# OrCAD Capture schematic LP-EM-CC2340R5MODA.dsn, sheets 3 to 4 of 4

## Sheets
3 3_Debugger Interface: size A3
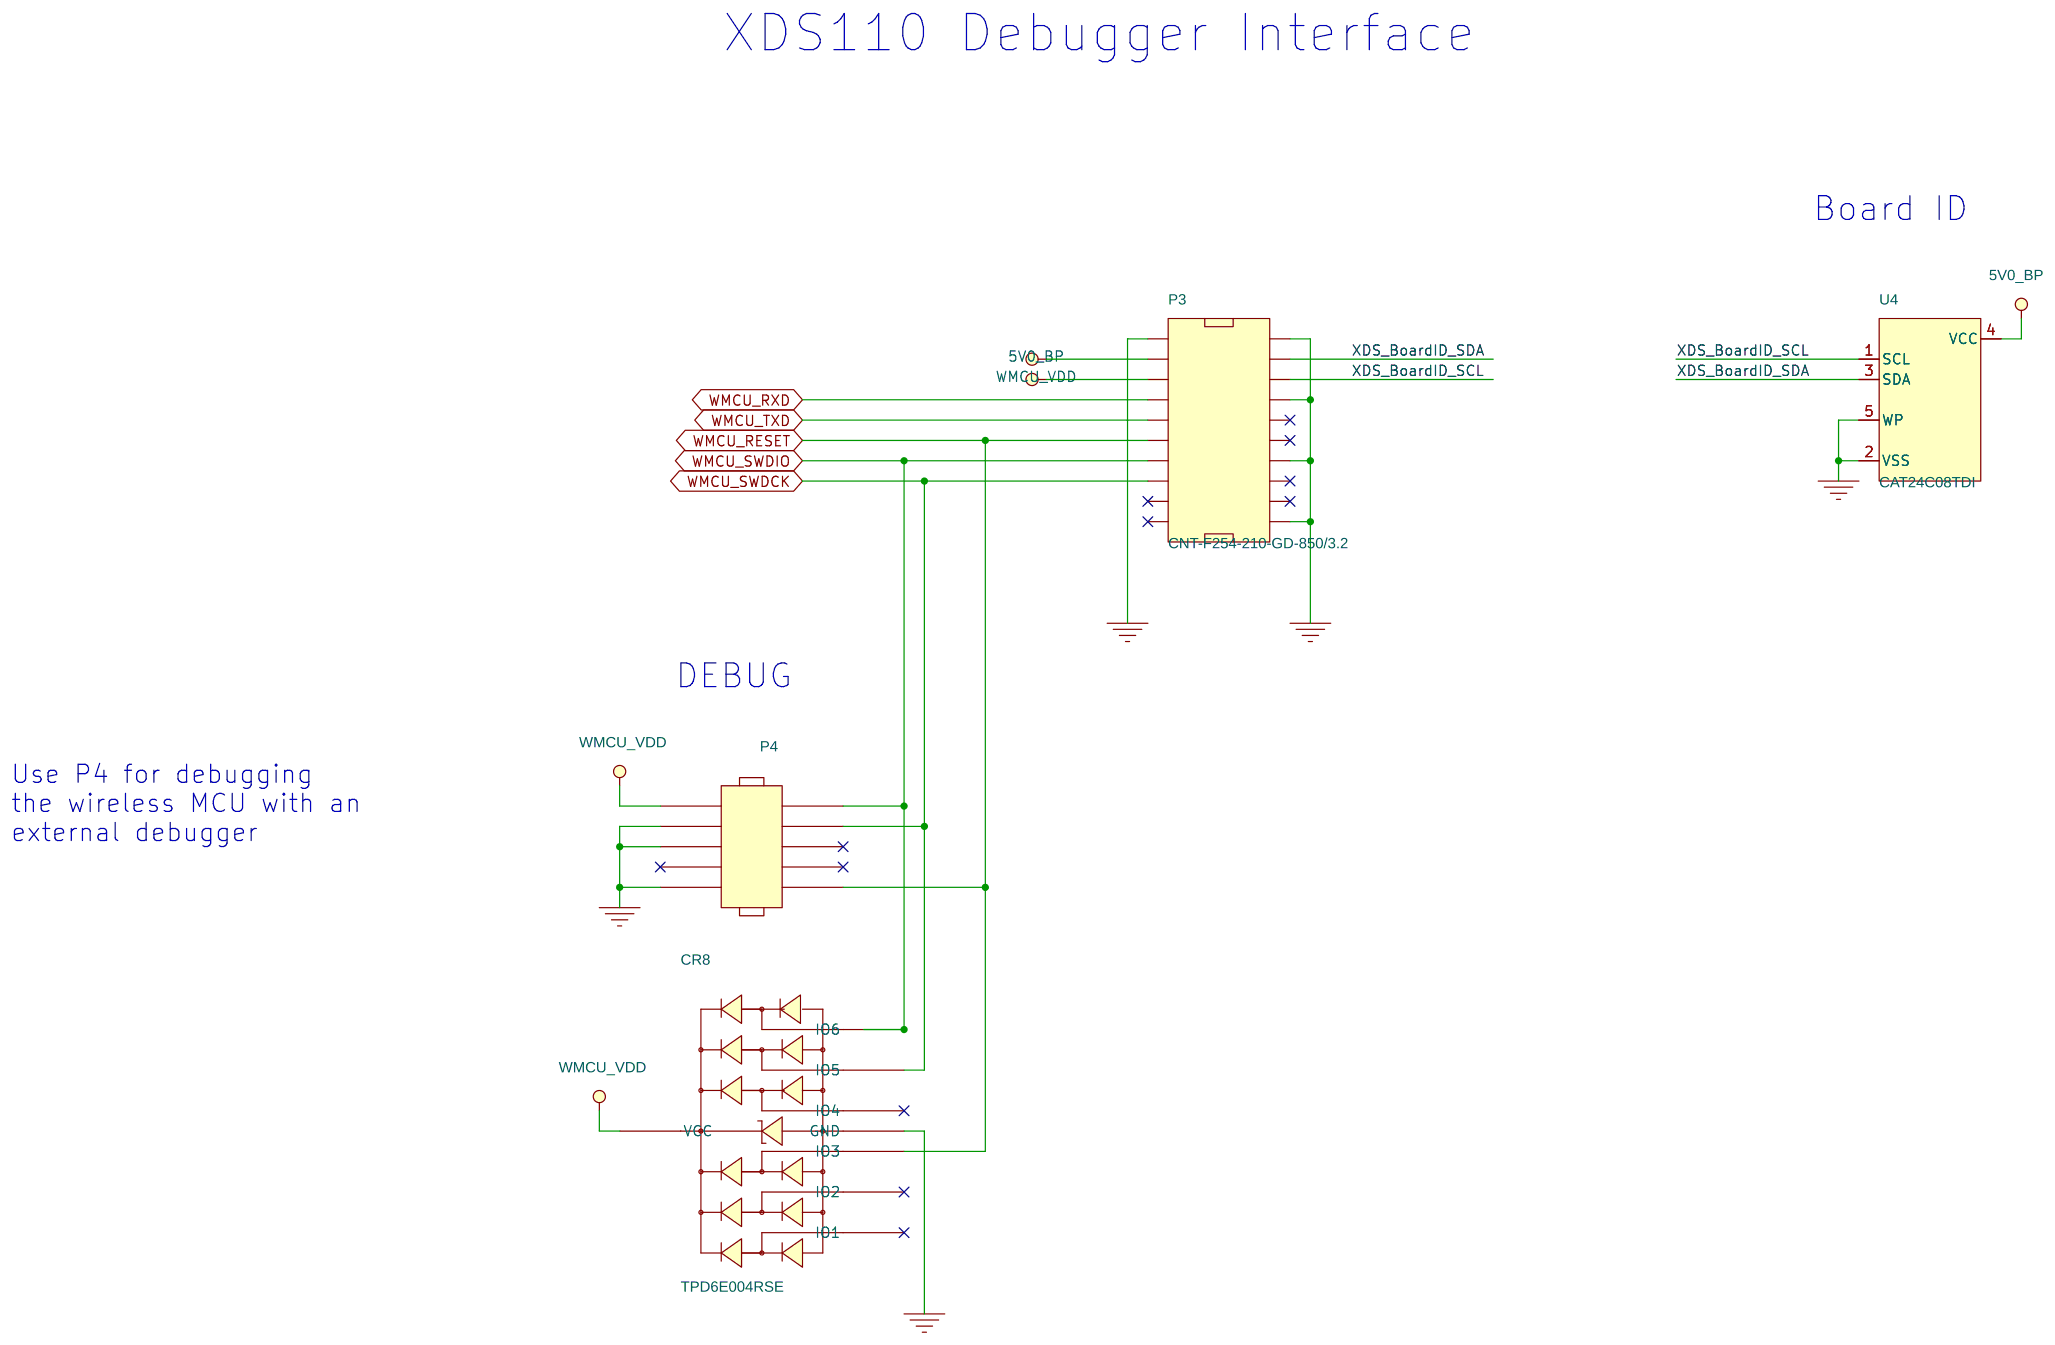
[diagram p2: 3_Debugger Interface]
4 4_Mech: size A3
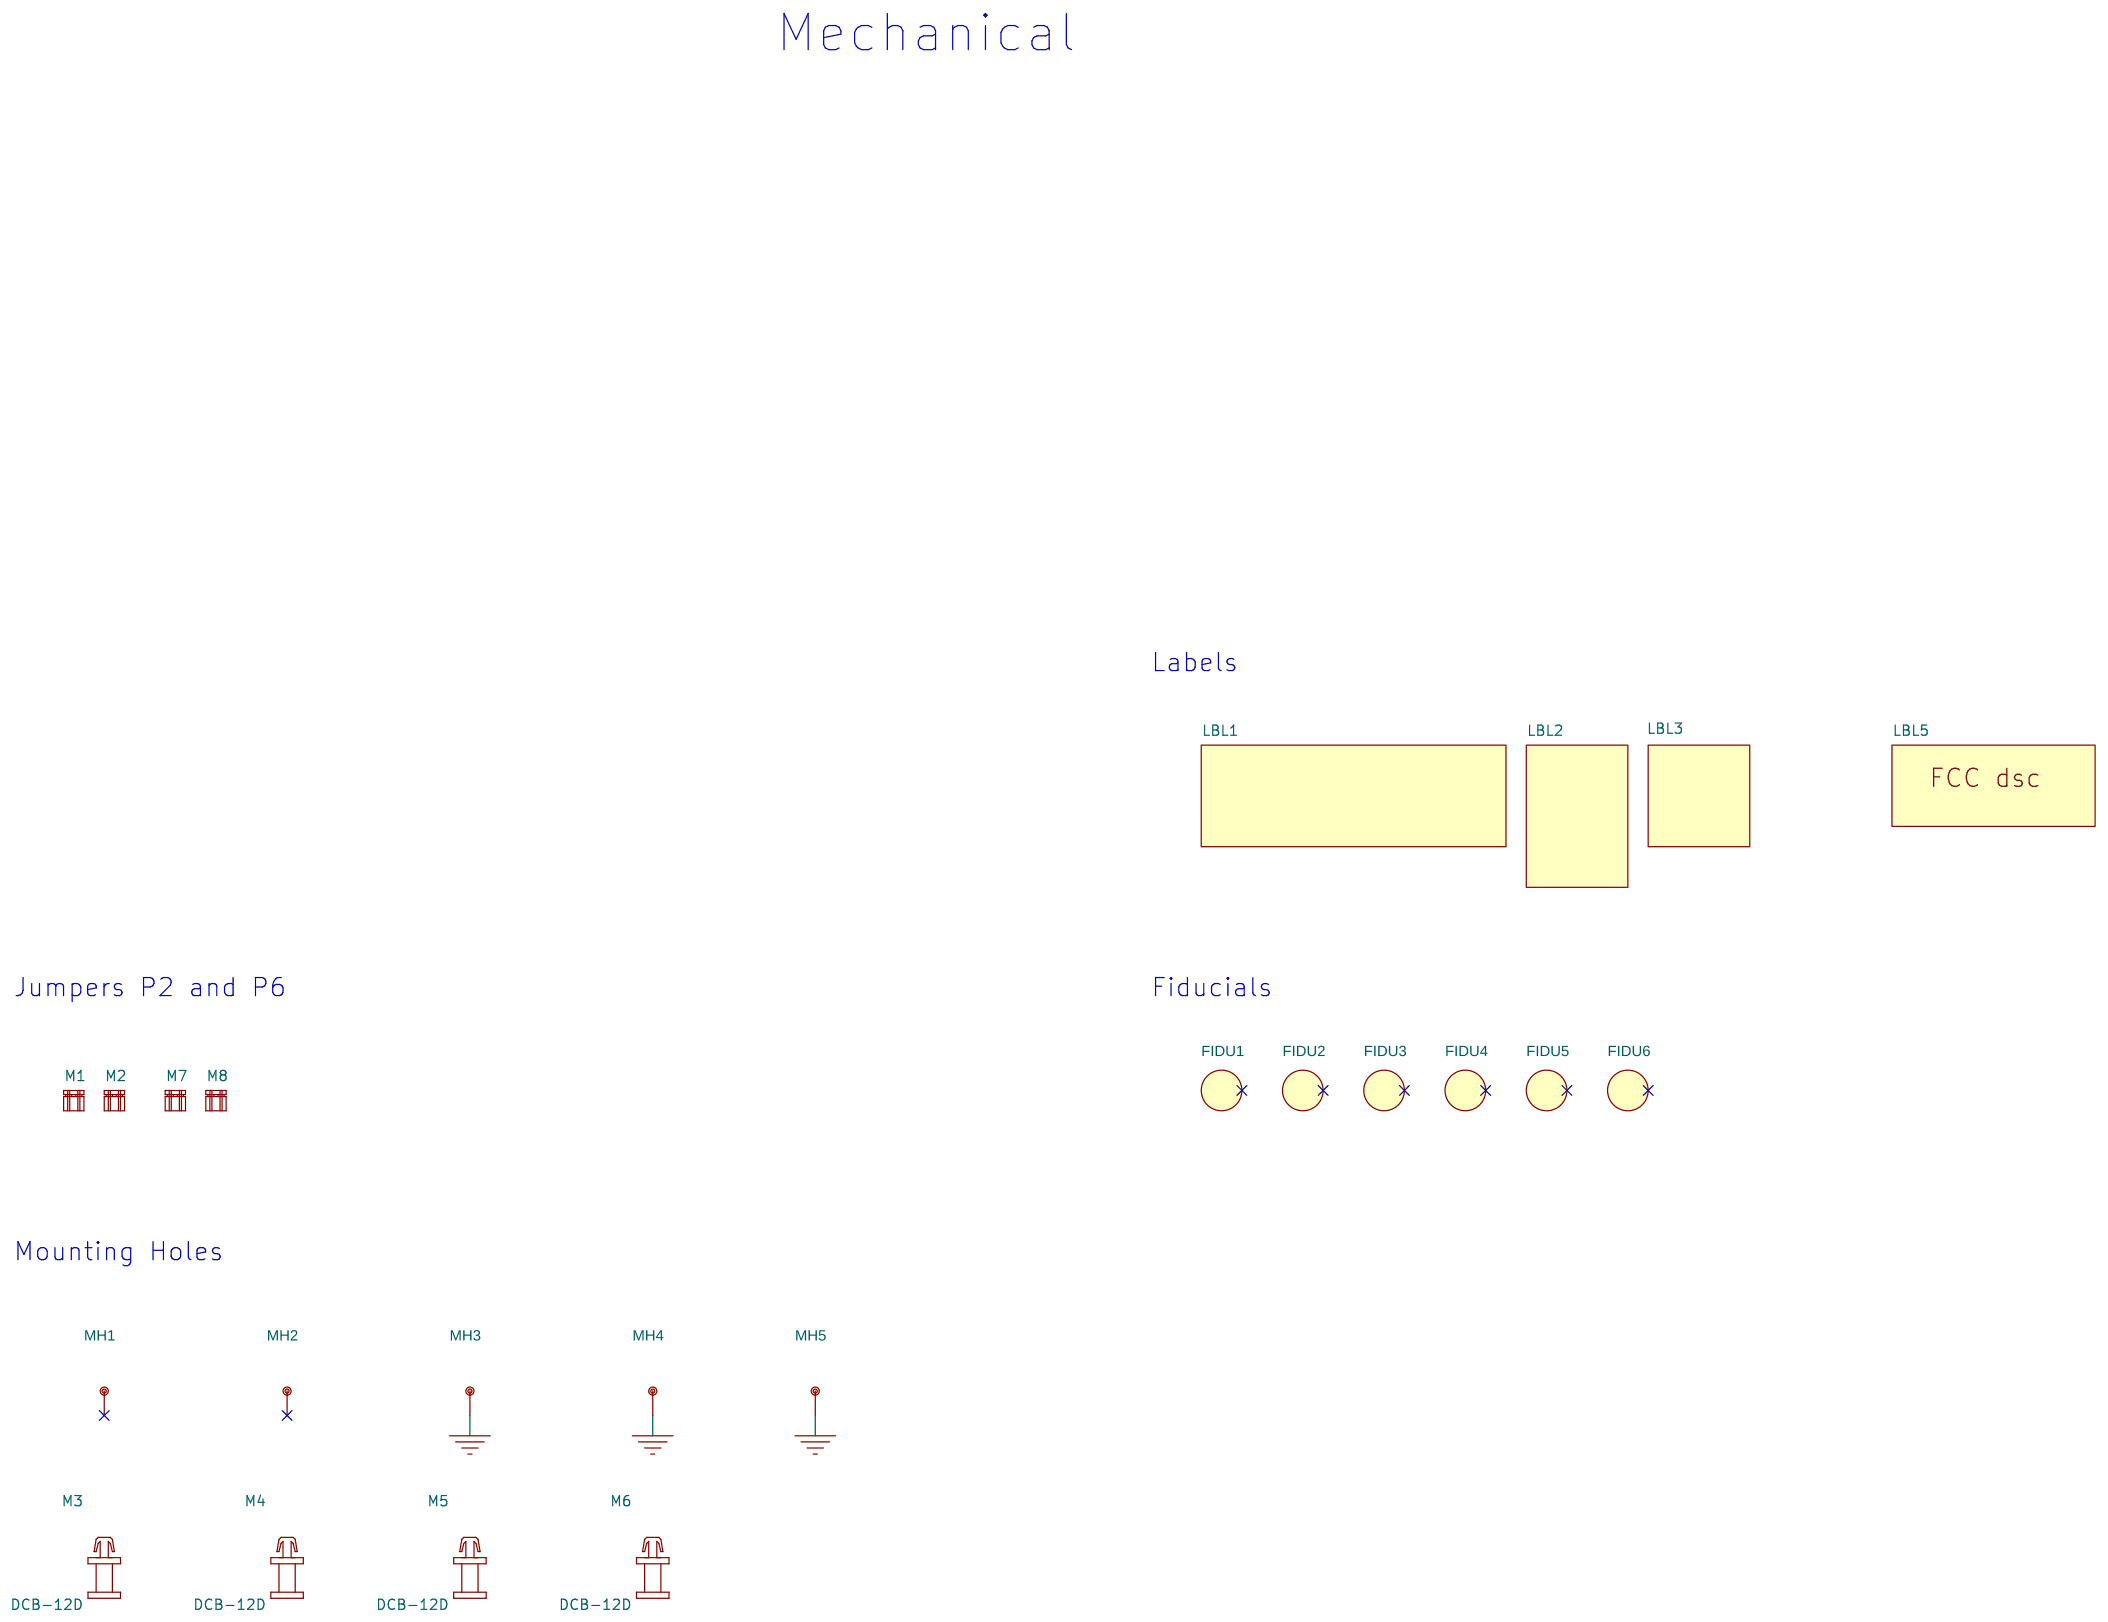
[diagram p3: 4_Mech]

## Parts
sheet 3_Debugger Interface
CR8  TPD6E004RSE  [QFNFC50P150X150X60-8A2N]
P3  CNT-F254-210-GD-850/3.2  [CNT_CNTF254210GD85032_A2B]
P4  FTSH-105-01-F-DV-K  [SAMTEC_FTSH-105-01-F-DV-K-10N]
U4  CAT24C08TDI  [SOT95P280X100-5A2N]
sheet 4_Mech
FIDU1  FIDU_1.27mm  [FID127X142]
FIDU2  FIDU_1.27mm  [FID127X142]
FIDU3  FIDU_1.27mm  [FID127X142]
FIDU4  FIDU_1.27mm  [FID127X142]
FIDU5  FIDU_1.27mm  [FID127X142]
FIDU6  FIDU_1.27mm  [FID127X142]
LBL1  TI_LOGO  [TI_LOGO_1]
LBL2  TRASH_7mm  [TRASH_7MM]
LBL3  ESD_LABEL_5x5mm  [ESD_LABEL_5X5]
LBL5  LABEL_FOR_EVALUATION_ONLY  [LABEL_FOR_EVALUATION_ONLY]
M1  SNT-100-BK-G  [SAMTEC_SNT100BKG]
M2  SNT-100-BK-G  [SAMTEC_SNT100BKG]
M3  DCB-12D  [MECH_DCB12D_A2B]
M4  DCB-12D  [MECH_DCB12D_A2B]
M5  DCB-12D  [MECH_DCB12D_A2B]
M6  DCB-12D  [MECH_DCB12D_A2B]
M7  SNT-100-BK-G  [SAMTEC_SNT100BKG]
M8  SNT-100-BK-G  [SAMTEC_SNT100BKG]
MH1  HOLE_3.2mm_PAD_3.8mm_PTH  [MTG320_380]
MH2  HOLE_3.2mm_PAD_3.8mm_PTH  [MTG320_380]
MH3  HOLE_3.2mm_PAD_3.8mm_PTH  [MTG320_380]
MH4  HOLE_3.2mm_PAD_3.8mm_PTH  [MTG320_380]
MH5  HOLE_1.1mm_PTH  [MTG110_170]

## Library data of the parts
CR8 = DIODE_TVS_TPD6E004_QFN8_V1: DIODE, PROTECTION, ESD ARRAY - 6 CHANNELS, VCC:0.9V TO 5.5V, VBR:7V, -40DEGC/+85DEGC, QFN8, SMD; ALT_SYMBOLS: QFNFC50P150X150X60-8A2L,QFNFC50P150X150X60-8A2M; Additional Datasheet URL: https://www.ti.com/product/TPD6E004; AutoDoc File: https://notefied-dynamic-precision.com/DB/Apps/Desktop/Item/Object.aspx?id=74721; BU Name: DYNAMIC PRECISION GDANSK; Budget Currency: USD; Budget Price: 0.27; Budgetary Price: .16 USD; CLASS: IC; Client Status: UNDER_REVIEW; Country of Origin: China; Datasheet URL: https://www.ti.com/lit/gpn/TPD6E004; Datasheet URL 1: http://www.ti.com/lit/ds/symlink/tpd6e004.pdf; Datasheet URL 2: http://www.ti.com/litv/pdf/mpqf207b; FPLIST: QFN50P150X150X60-8N,QFN50P150X150X60-8AN; Lead Time: 12; Mass: 0.002839255g; Max Oper Temp: +85DEGC; Maximum Operating Temperature: +85DEGC; Min Oper Temp: -40DEGC; Minimum Operating Temperature: -40DEGC; Mounting Type: SMD; NOTEfied URL: https://dev-webinterface.dpserver.no/item/7366948; PCB Package: QFN8; Packing Size: 3000; Packing Type: Tape & Reel; Part Number: 14-05493; Part Type: Diode|PROTECTION; REACH/SVHC Compliance: Compliant; REACH/SVHC Details: SVHC List Version Jun 20, 2016; REACH/SVHC Source: Material Declaration; REACH/SVHC Status: Unaffected; ROHS: Compliant; Rated Power: N/A; Rated Voltage: 7V; Revision: R029; RoHS Status: ROHS_COMPLIANT; Rtd Power: N/A; Rtd Voltage: 7V; Status: Released; Texas Part Status: Under Review; Type: Diode; Vendor: TEXAS INSTRUMENTS; Vendor Part Number: TPD6E004RSER; Vendor Part Status: Active; Weight: 0.0033g
P3 = CONN_HEADER_2X10_J_S_V1: CONNECTOR, HEADER, FEMALE, RIGHT ANGLE, 2 ROW(S), 20 PIN(S), PITCH 2.54mm, PTH; ALT_SYMBOLS: CNT_CNTF254210GD85032_A2A,CNT_CNTF254210GD85032_A2C; Additional Datasheet URL: http://yccnt.com/cpzx/info_56.aspx?itemid=1264&lcid=28&cid=29; Country of Origin: Missing Info; Datasheet URL: http://yccnt.com/uploadfiles/2017/08/201708261737473747.pdf; Maximum Operating Temperature: +105DEGC; Minimum Operating Temperature: -40DEGC; Mounting Type: PTH; NOTEfied URL: https://dev-webinterface.dpserver.no/item/24885457; Number of Positions: 20; Number of Rows: 2; Packing Size: N/A; Packing Type: Missing Info; Part Number: 06-08434; Part Type: Connector|HEADER|STANDARD; Pitch: 2.54mm; REACH/SVHC Compliance: Missing Info; REACH/SVHC Details: N/A; REACH/SVHC Source: N/A; REACH/SVHC Status: Missing Info; ROHS: Compliant; Rated Current: 3A; Rated Voltage: 500V; Revision: R005; Status: Released; Texas Part Status: Under Review; Type: Connector; Vendor: CNT CONNECTORS; Vendor Part Status: Active
P4 = CONN_HEADER_2X5: CONNECTOR, HEADER, MALE, STRAIGHT, 2 ROW(S), 10 PIN(S), PITCH 1.27mm, SMD; ALT_SYMBOLS: SAMTEC_FTSH10501FDVK_A2L,SAMTEC_FTSH10501FDVK_A2M,SAMTEC_FTSH10501FDVK_B2L,SAMTEC_FTSH10501FDVK_B2M; Additional Datasheet URL: https://www.samtec.com/products/ftsh-105-01-f-dv-k; AutoDoc File: http://notefied-dynamic-precision.com/DB/Apps/Desktop/Item/Object.aspx?id=50836; Budget Currency: USD; Budget Price: 1.700; Budgetary Price: 2.07959 USD; CLASS: IO; Country of Origin: China, Costa Rica, Malaysia, Singapore, Taiwan, United States, Vietnam; Datasheet URL: https://suddendocs.samtec.com/catalog_english/ftsh_smt.pdf; Datasheet URL 1: http://www.samtec.com/documents/webfiles/cpdf/FTSH-1XX-XX-XXX-DV-XXX-MKT.pdf; Datasheet URL 2: http://www.samtec.com/documents/webfiles/pdf/FTSH_SMT.PDF; FPLIST: SAMTEC_FTSH-105-01-F-DV-K-10N,SAMTEC_FTSH-105-01-F-DV-K-10L,SAMTEC_FTSH-105-01-F-DV-K-10M; Lead Time: 14; LifeCycle Status: MATURITY; MPN Status: ACTIVE; Manufacturer: SAMTEC; Mass: 0.31700g; Max Oper Temp: +125DEGC; Maximum Operating Temperature: +125DEGC; Min Oper Temp: -55DEGC; Minimum Operating Temperature: -55DEGC; Mounting Type: SMD; NOTE Status: PREFERRED; NOTEfied URL: https://dev-webinterface.dpserver.no/item/7308603; No Of Pos: 10; No Of Rows: 2; Number of Positions: 10; Number of Rows: 2; Old Footprint: SAMTEC_FTSH-105-01-F-DV-K-10N,CONN_MALE_2X5; Packing Size: 92; Packing Type: Tube; Part Number: 06-00166; Part Type: Connector|HEADER|STANDARD; Pitch: 1.27mm; REACH/SVHC Compliance: Compliant; REACH/SVHC Details: SVHC List Version Jun 20, 2016; REACH/SVHC Source: Material Declaration; REACH/SVHC Status: Unaffected; ROHS: Compliant; Rated Current: 3.4A; Revision: R034; RoHS Status: ROHS_COMPLIANT; Rtd Current: 1.75A; Status: Released; Texas Part Status: Under Review; Type: Connector; Vendor: SAMTEC; Vendor Part Status: Active; WEIGHT: 0.65614g
U4 = IC_EEPROM_CAT24C08_TSOT23-5: IC, MEMORY, EEPROM, SERIAL, I2C, 8kbit, 1k X 8bit, 900ns, 1.7V TO 5.5V, TSOT23-5, SMD; ALT_SYMBOLS: SOT95P280X100-5A2L,SOT95P280X100-5A2M; Additional Datasheet URL: https://www.onsemi.com/products/timing-logic-memory/memory/eeprom-memory/cat24c08; Budgetary Price: .1867 USD; Country of Origin: Thailand; Datasheet URL: https://www.onsemi.com/download/data-sheet/pdf/cat24c01-d.pdf; Lead Time: 23; Mass: 0.01268g; Maximum Operating Temperature: +85DEGC; Minimum Operating Temperature: -40DEGC; Mounting Type: SMD; NOTEfied URL: https://dev-webinterface.dpserver.no/item/25158614; PCB Package: TSOT23-5; Packing Size: 3000; Packing Type: Tape & Reel; Part Number: 18-36044; Part Type: IC|EEPROM|SERIAL|I2C; REACH/SVHC Compliance: Compliant; REACH/SVHC Details: SVHC List Version Jan 16, 2020; REACH/SVHC Source: REACH Declaration; REACH/SVHC Status: Unaffected; ROHS: Compliant; Rated Voltage: 1.7V TO 5.5V; Revision: R007; Status: Released; Texas Part Status: Under Review; Type: IC; Vendor: ONSEMI; Vendor Part Number: CAT24C08TDI-GT3; Vendor Part Status: Active
FIDU1-FIDU6 = FIDMARK: NON COMPONENT, FIDUCIAL MARK, ROUND 1.27MM, SMD; Additional Datasheet URL: N/A; CLASS: IO; Country of Origin: Missing Info; Datasheet URL: N/A; Mass: N/A; Mounting Type: SMD; NOTEfied URL: https://dev-webinterface.dpserver.no/item/7504224; Packing Size: N/A; Packing Type: Missing Info; Part Number: 19-00300; Part Type: Non Component|FIDUCIAL; ROHS: Not Applicable; Revision: R020; Status: Released; Texas Part Status: Under Review; Type: Non Component; Vendor: NON_COMPONENT; Vendor Part Number: FIDUCIAL_1.27mm; Vendor Part Status: Active
LBL1 = TI_LOGO_V1: NON COMPONENT, LABEL, TEXAS INSTRUMENTS LOGO; Additional Datasheet URL: N/A; AutoDoc File: https://notefied-dynamic-precision.com/DB/Apps/Desktop/Item/Object.aspx?id=87770; BU Name: TEXAS INSTRUMENTS NORWAY; Country of Origin: Missing Info; Datasheet URL: N/A; Mass: N/A; Mounting Type: NOT APPLY; NOTEfied URL: https://dev-webinterface.dpserver.no/item/7504541; Notes: Custom Item; Packing Size: N/A; Packing Type: Missing Info; Part Number: 19-00350; Part Type: Non Component|LABEL; ROHS: Not Applicable; Revision: R023; Status: Released; Texas Part Status: Under Review; Type: Non Component; Vendor: NON_COMPONENT; Vendor Part Status: Active
LBL2 = TRASH_V2: NON COMPONENT, LABEL, TRASH 7mm; Additional Datasheet URL: N/A; Country of Origin: Missing Info; Datasheet URL: N/A; Mass: N/A; Mounting Type: NOT APPLY; NOTEfied URL: https://dev-webinterface.dpserver.no/item/14983721; Packing Size: N/A; Packing Type: Missing Info; Part Number: 19-01044; Part Type: Non Component|LABEL; ROHS: Not Applicable; Revision: R016; Status: Released; Texas Part Status: Under Review; Type: Non Component; Vendor: NON_COMPONENT; Vendor Part Status: Active
LBL3 = ESD_LABEL: NON COMPONENT, LABEL, ESD, 5 X 5 mm; Additional Datasheet URL: N/A; Country of Origin: Missing Info; Datasheet URL: N/A; Mass: N/A; Maximum Operating Temperature: N/A; Minimum Operating Temperature: N/A; Mounting Type: NOT APPLY; NOTEfied URL: https://dev-webinterface.dpserver.no/item/7504774; Packing Size: N/A; Packing Type: Missing Info; Part Number: 19-00471; Part Type: Non Component|LABEL; ROHS: Not Applicable; Revision: R009; Status: Released; Type: Non Component; Vendor: NON_COMPONENT; Vendor Part Status: Active
LBL5 = LABEL_FOR_EVALUATOIN_ONLY: NON COMPONENT, LABEL, FOR EVALUATION ONLY, NOT FCC APPROVED FOR RESALE; Additional Datasheet URL: N/A; AutoDoc File: https://notefied-dynamic-precision.com/DB/Apps/Desktop/Item/Object.aspx?id=115268; BU Name: TEXAS INSTRUMENTS NORWAY; Country of Origin: Missing Info; Datasheet URL: N/A; Mass: N/A; Maximum Operating Temperature: N/A; Minimum Operating Temperature: N/A; Mounting Type: NOT APPLY; NOTEfied URL: https://dev-webinterface.dpserver.no/item/7505603; Notes: Custom Item; Packing Size: N/A; Packing Type: Missing Info; Part Number: 19-00830; Part Type: Non Component|LABEL; REACH/SVHC Compliance: Missing Info; REACH/SVHC Details: N/A; REACH/SVHC Source: N/A; REACH/SVHC Status: Missing Info; ROHS: Not Applicable; Revision: R023; Status: Released; Texas Part Status: Under Review; Type: Non Component; Vendor: NON_COMPONENT; Vendor Part Status: Active
M1 M2 M7 M8 = MECH_SHUNT_JUMPER_V1: MECHANIC, SHUNT, CURRENT RATING 4.3A PER PIN, 2.54 X 5.08 X 6.1mm, BLACK; Additional Datasheet URL: https://www.samtec.com/products/snt-100-bk-g; AutoDoc File: https://notefied-dynamic-precision.com/DB/Apps/Desktop/Item/Object.aspx?id=104092; BU Name: DYNAMIC PRECISION GDANSK; Budget Currency: USD; Budget Price: 0.146; Budgetary Price: .19442 USD; Client Status: UNDER_REVIEW; Country of Origin: China, Costa Rica, Malaysia, Singapore, Taiwan, United States, Vietnam; Datasheet URL: https://suddendocs.samtec.com/catalog_english/snt.pdf; Datasheet URL 1: http://suddendocs.samtec.com/catalog_english/snt.pdf; Datasheet URL 2: http://suddendocs.samtec.com/prints/snt-100-xx-x-x-mkt.pdf; Lead Time: 9; Mass: 0.52432g; Max Oper Temp: +125DEGC; Maximum Operating Temperature: +125DEGC; Min Oper Temp: -55DEGC; Minimum Operating Temperature: -55DEGC; Mounting Type: NOT APPLY; NOTEfied URL: https://dev-webinterface.dpserver.no/item/7503385; Packing Size: 1; Packing Type: Bulk; Part Number: 19-00498; Part Type: Mechanic|SHUNT; REACH/SVHC Compliance: Compliant; REACH/SVHC Details: SVHC List Version Dec 17, 2015; REACH/SVHC Source: Material Declaration; REACH/SVHC Status: Unaffected; REACH/SVHC_COMPLIANCE: COMPLIANT; REACH/SVHC_DETAILS: SVHC LIST VERSION Dec 17, 2015; REACH/SVHC_SOURCE: MATERIAL DECLARATION; REACH/SVHC_STATUS: UNAFFECTED; ROHS: Compliant; Rated Current: 4.3A; Revision: R028; RoHS Status: ROHS_COMPLIANT; Rtd Current: 4.3A; Status: Released; Texas Part Status: Under Review; Type: Mechanic; Vendor: SAMTEC; Vendor Part Status: Active; Weight: 0.11724g
M3-M6 = MECH_SPACERS_SUPPORT_V1: MECHANIC, ACCESSORY, SPACER SUPPORT, PCB DIA. 3mm, NYLON 66, NPTH; Additional Datasheet URL: https://www.kangyang-europe.com/product/pc-board-hardware/dcb-12d/; Country of Origin: Missing Info; Datasheet URL: https://www.kangyang-europe.com/wp-content/uploads/2020/02/DCB-HD.pdf; Maximum Operating Temperature: N/A; Minimum Operating Temperature: N/A; Mounting Type: NPTH; NOTEfied URL: https://dev-webinterface.dpserver.no/item/44342418; Notes: Custom libraries; Packing Size: 1000; Packing Type: Missing Info; Part Number: 13-07898; Part Type: Mechanic|ACCESSORY; REACH/SVHC Compliance: Compliant; REACH/SVHC Details: SVHC List Version Jul 7, 2017; REACH/SVHC Source: REACH Declaration; REACH/SVHC Status: Unaffected; ROHS: Compliant; Revision: R018; Status: Released; Texas Part Status: Under Review; Type: Mechanic; Vendor: SUZHOU SOLY ELECTRICIAN; Vendor Part Status: Active
MH1-MH4 = HOLE_PTH: NON COMPONENT, HOLE 3.2mm, PLATED, PAD SIZE 3.8mm; Additional Datasheet URL: N/A; Country of Origin: Missing Info; Datasheet URL: N/A; Mass: N/A; Mounting Type: NOT APPLY; NOTEfied URL: https://dev-webinterface.dpserver.no/item/7503683; Packing Size: N/A; Packing Type: Missing Info; Part Number: 19-00083; Part Type: Non Component|HOLE|PLATED; ROHS: Not Applicable; Revision: R022; Status: Released; Type: Non Component; Vendor: NON_COMPONENT; Vendor Part Status: Active
MH5 = HOLE_PTH: NON COMPONENT, HOLE 1.1mm, PLATED, PAD SIZE 1.7mm; Additional Datasheet URL: N/A; Country of Origin: Missing Info; Datasheet URL: N/A; Mass: N/A; Mounting Type: NOT APPLY; NOTEfied URL: https://dev-webinterface.dpserver.no/item/7503643; Packing Size: N/A; Packing Type: Missing Info; Part Number: 19-00062; Part Type: Non Component|HOLE|PLATED; ROHS: Not Applicable; Revision: R007; Status: Released; Type: Non Component; Vendor: NON_COMPONENT; Vendor Part Number: HOLE_1.1mm_PLATED; Vendor Part Status: Active

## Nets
5V0_BP: P3.3 U4.4(VCC) ; also on sheet 2
GND: CR8.4(GND) MH3.1 MH4.1 MH5.1 P3.1 P3.2 P3.8 P3.14 P3.20 P4.3 P4.5 P4.9 U4.2(VSS) U4.5(WP) ; also on sheet 1 2
DIO6: P3.9 ; also on sheet 1 2
DIO20: P3.7 ; also on sheet 1 2
WMCU_RESET: CR8.3(IO3) P3.11 P4.10 ; also on sheet 1 2
WMCU_SWDCK: CR8.6(IO5) P3.15 P4.4 ; also on sheet 1 2
WMCU_SWDIO: CR8.7(IO6) P3.13 P4.2 ; also on sheet 1 2
WMCU_VDD: CR8.8(VCC) P3.5 P4.1 ; also on sheet 1 2
XDS_BoardID_SCL: P3.6 U4.1(SCL)
XDS_BoardID_SDA: P3.4 U4.3(SDA)

Not connected (* = marked no-connect by the designer): CR8 1(IO1)* 2(IO2)* 5(IO4)*; FIDU1 1*; FIDU2 1*; FIDU3 1*; FIDU4 1*; FIDU5 1*; FIDU6 1*; MH1 1*; MH2 1*; P3 10* 12* 16* 17* 18* 19*; P4 6* 7* 8*

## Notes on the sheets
sheet 3
- XDS110 Debugger Interface
- Board ID
- DEBUG
- Use P4 for debugging
  the wireless MCU with an
  external debugger
sheet 4
- Mechanical
- Labels
- Jumpers P2 and P6
- Fiducials
- Mounting Holes
